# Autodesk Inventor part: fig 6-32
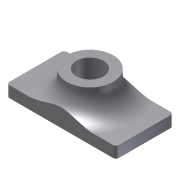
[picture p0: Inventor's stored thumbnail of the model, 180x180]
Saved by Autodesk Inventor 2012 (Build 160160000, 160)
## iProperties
Created: 2004-05
Part Number: fig 6-32
Document SubType Name: Modeling
Designer: CADCIM Technologies
Manufacturer: Standard
Standards Organization: Custom
Density: 1 g/cm^3
Material: Default
Author: CADCIM Technologies
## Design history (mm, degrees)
sketch "Sketch1"
  geometry: L1 (-39.276, -18.692)-(33.721, -18.692); L2 (33.721, -18.692)-(33.721, 19.728); L3 (33.721, 19.728)-(-39.276, 19.728); L4 (-39.276, 19.728)-(-39.276, -18.692)
  constraints: 8 end point, 2 parallel, 1 horizontal, 1 perpendicular
extrude "Extrusion1" new body sketch "Sketch1" distance "d0" = 7.5; taper "d1" = 0 deg
fillet "Fillet1" dims "d2" = 2
sketch "Sketch2"
  geometry: C1 r 15.456 at (-2.778, 0.518)
  constraints: 1 centre point
extrude "Extrusion2" join sketch "Sketch2" distance "d3" = 17.25; taper "d4" = 0 deg
hole "Hole1" diameter "d8" = 18; stored, may be unused: countersink angle "d12" = 90 deg, drill point angle "d14" = 118 deg; dims "d6" = 10, "d7" = 10, "d9" = 6, "d10" = 4, "d11" = 2, "d13" = 8
fillet "Fillet2" dims "d5" = 14
body "Solid1"
